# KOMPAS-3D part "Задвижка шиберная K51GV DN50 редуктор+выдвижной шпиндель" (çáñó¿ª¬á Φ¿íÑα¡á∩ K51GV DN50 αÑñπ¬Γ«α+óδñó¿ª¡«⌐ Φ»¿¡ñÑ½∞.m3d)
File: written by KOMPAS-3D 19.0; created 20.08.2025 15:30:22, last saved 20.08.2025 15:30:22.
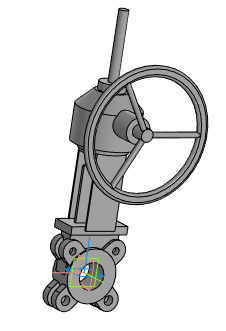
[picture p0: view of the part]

Document properties: Полное имя файла: Задвижка шиберная K51GV DN50 редуктор+выдвижной шпиндель.a3d

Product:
- Part/product: Задвижка шиберная K51GV DN50 редуктор+выдвижной шпиндель
    Масса: 16.0167

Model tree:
1. Операция без истории:1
